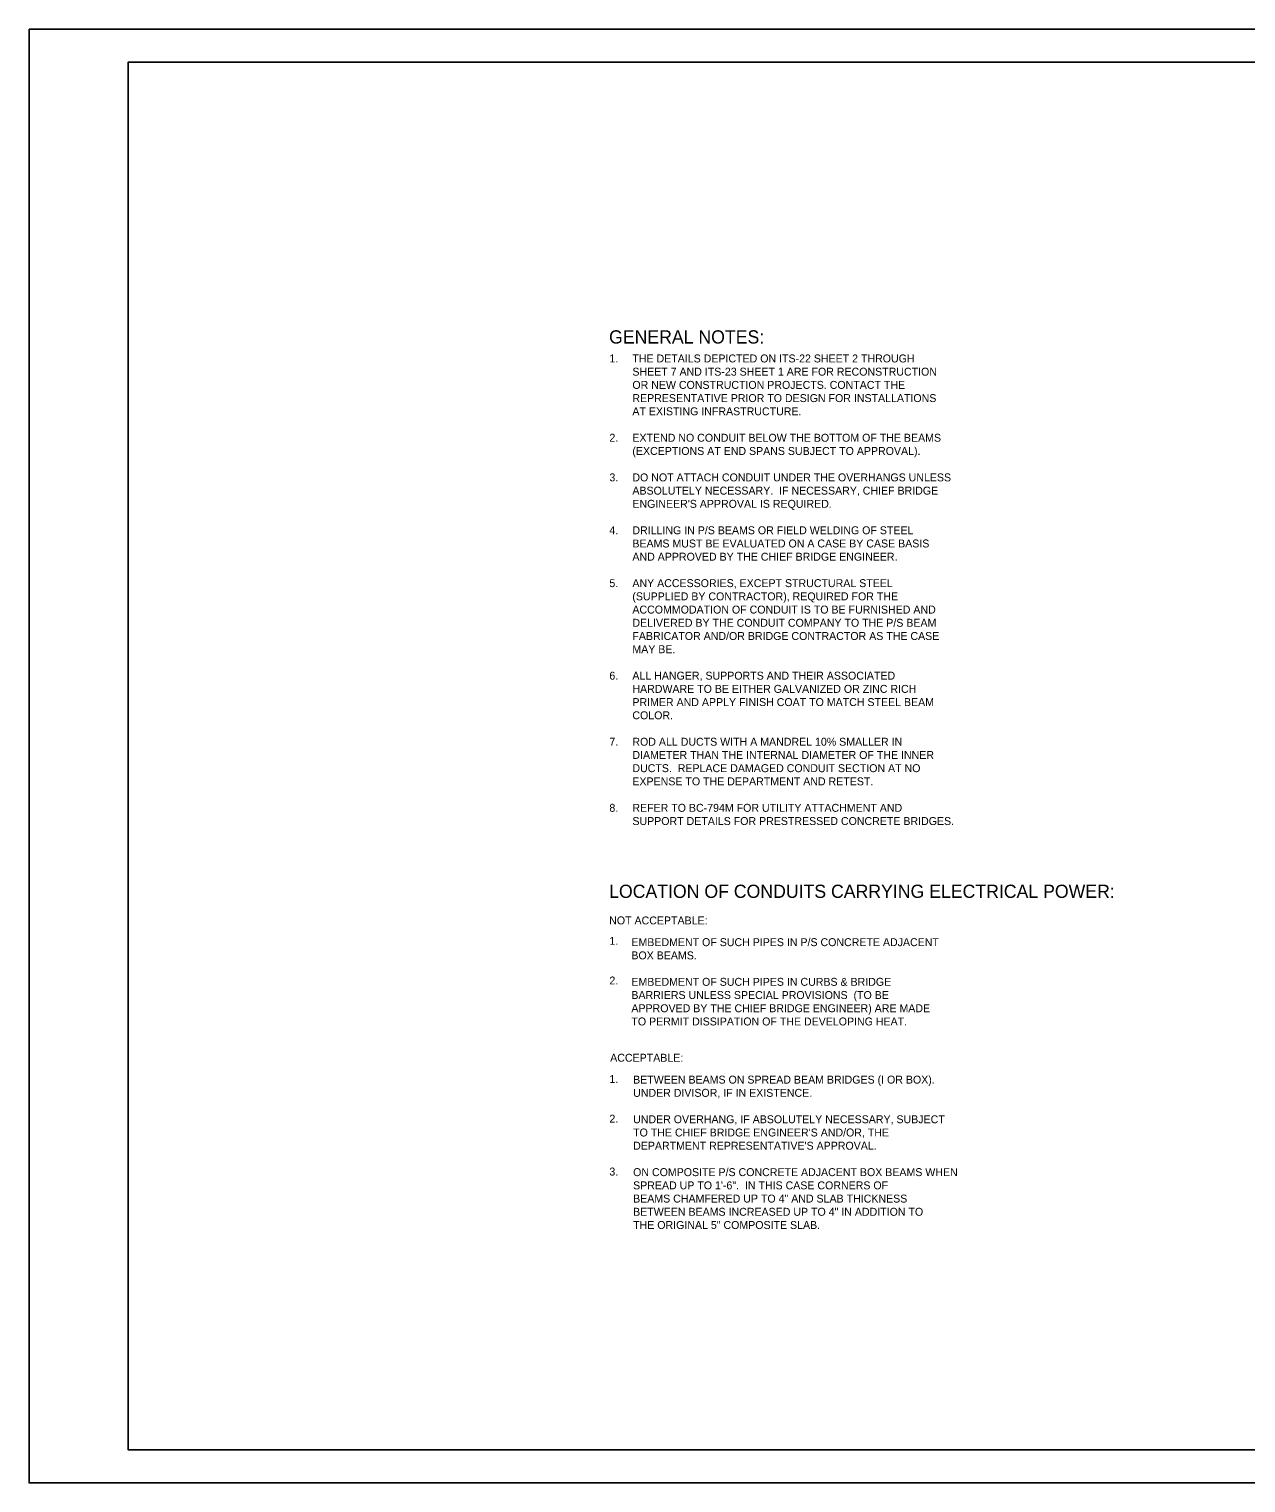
# Model space of a CAD drawing. Extents: x 1299104.8 to 1299141.6, y 239639.8 to 239661.8.
# Drawn here: x 1299104.8 to 1299123.22, y 239639.79 to 239661.79 of the extents above; entities that cross this region are included whole.
import ezdxf

# ---------------------------------------------------------------- set-up
doc = ezdxf.new("R2010")
doc.units = 0
for name, color, linetype in [('DIM TXT', 7, 'Continuous'), ('GS_plotshape_p', 7, 'Continuous'), ('Level 1', 7, 'Continuous')]:
    doc.layers.add(name, color=color, linetype=linetype)

msp = doc.modelspace()

# ---------------------------------------------------------------- linework, layer by layer
at = {"layer": 'GS_plotshape_p'}
msp.add_lwpolyline([(1299104.802, 239661.791), (1299138.802, 239661.791), (1299138.802, 239639.791), (1299104.802, 239639.791)], close=True, dxfattribs=at)
at = {"layer": 'Level 1'}
msp.add_lwpolyline([(1299138.302, 239640.291), (1299106.302, 239640.291), (1299106.302, 239661.291), (1299138.302, 239661.291)], close=True, dxfattribs=at)

# ---------------------------------------------------------------- texts
at = {"layer": 'DIM TXT'}
for s, height, p in [('GENERAL NOTES:', 0.2, (1299113.58, 239657.033)), ('1.', 0.12, (1299113.585, 239656.747)), ('THE DETAILS DEPICTED ON ITS-22 SHEET 2 THROUGH ', 0.12, (1299113.933, 239656.747)), ('SHEET 7 AND ITS-23 SHEET 1 ARE FOR RECONSTRUCTION ', 0.12, (1299113.933, 239656.547)), ('OR NEW CONSTRUCTION PROJECTS. CONTACT THE ', 0.12, (1299113.933, 239656.347)), ('REPRESENTATIVE PRIOR TO DESIGN FOR INSTALLATIONS ', 0.12, (1299113.933, 239656.147)), ('AT EXISTING INFRASTRUCTURE.', 0.12, (1299113.933, 239655.947)), ('2.', 0.12, (1299113.585, 239655.547)), ('(EXCEPTIONS AT END SPANS SUBJECT TO APPROVAL). ', 0.12, (1299113.933, 239655.347)), ('EXTEND NO CONDUIT BELOW THE BOTTOM OF THE BEAMS ', 0.12, (1299113.933, 239655.547)), ('3.', 0.12, (1299113.585, 239654.947)), ('DO NOT ATTACH CONDUIT UNDER THE OVERHANGS UNLESS ', 0.12, (1299113.933, 239654.947)), ('ABSOLUTELY NECESSARY.  IF NECESSARY, CHIEF BRIDGE ', 0.12, (1299113.933, 239654.747)), ("ENGINEER'S APPROVAL IS REQUIRED. ", 0.12, (1299113.933, 239654.547)), ('4.', 0.12, (1299113.585, 239654.147)), ('DRILLING IN P/S BEAMS OR FIELD WELDING OF STEEL ', 0.12, (1299113.933, 239654.147)), ('BEAMS MUST BE EVALUATED ON A CASE BY CASE BASIS ', 0.12, (1299113.933, 239653.947)), ('AND APPROVED BY THE CHIEF BRIDGE ENGINEER. ', 0.12, (1299113.933, 239653.747)), ('5.', 0.12, (1299113.585, 239653.347)), ('ANY ACCESSORIES, EXCEPT STRUCTURAL STEEL ', 0.12, (1299113.933, 239653.347)), ('(SUPPLIED BY CONTRACTOR), REQUIRED FOR THE ', 0.12, (1299113.933, 239653.147)), ('ACCOMMODATION OF CONDUIT IS TO BE FURNISHED AND ', 0.12, (1299113.933, 239652.947)), ('DELIVERED BY THE CONDUIT COMPANY TO THE P/S BEAM ', 0.12, (1299113.933, 239652.747)), ('FABRICATOR AND/OR BRIDGE CONTRACTOR AS THE CASE ', 0.12, (1299113.933, 239652.547)), ('MAY BE. ', 0.12, (1299113.933, 239652.347)), ('6.', 0.12, (1299113.585, 239651.947)), ('ALL HANGER, SUPPORTS AND THEIR ASSOCIATED ', 0.12, (1299113.933, 239651.947)), ('HARDWARE TO BE EITHER GALVANIZED OR ZINC RICH ', 0.12, (1299113.933, 239651.747)), ('PRIMER AND APPLY FINISH COAT TO MATCH STEEL BEAM ', 0.12, (1299113.933, 239651.547)), ('COLOR. ', 0.12, (1299113.933, 239651.347)), ('7.', 0.12, (1299113.585, 239650.947)), ('ROD ALL DUCTS WITH A MANDREL 10% SMALLER IN ', 0.12, (1299113.933, 239650.947)), ('DIAMETER THAN THE INTERNAL DIAMETER OF THE INNER ', 0.12, (1299113.933, 239650.747)), ('DUCTS.  REPLACE DAMAGED CONDUIT SECTION AT NO ', 0.12, (1299113.933, 239650.547)), ('EXPENSE TO THE DEPARTMENT AND RETEST.', 0.12, (1299113.933, 239650.347)), ('8.', 0.12, (1299113.585, 239649.947)), ('REFER TO BC-794M FOR UTILITY ATTACHMENT AND ', 0.12, (1299113.933, 239649.947)), ('SUPPORT DETAILS FOR PRESTRESSED CONCRETE BRIDGES.', 0.12, (1299113.933, 239649.747)), ('LOCATION OF CONDUITS CARRYING ELECTRICAL POWER:', 0.2, (1299113.581, 239648.644)), ('NOT ACCEPTABLE:', 0.12, (1299113.582, 239648.243)), ('1.', 0.12, (1299113.585, 239647.934)), ('EMBEDMENT OF SUCH PIPES IN P/S CONCRETE ADJACENT ', 0.12, (1299113.918, 239647.914)), ('BOX BEAMS.  ', 0.12, (1299113.918, 239647.714)), ('2.', 0.12, (1299113.585, 239647.334)), ('EMBEDMENT OF SUCH PIPES IN CURBS & BRIDGE ', 0.12, (1299113.918, 239647.314)), ('BARRIERS UNLESS SPECIAL PROVISIONS  (TO BE ', 0.12, (1299113.918, 239647.114)), ('APPROVED BY THE CHIEF BRIDGE ENGINEER) ARE MADE ', 0.12, (1299113.918, 239646.914)), ('TO PERMIT DISSIPATION OF THE DEVELOPING HEAT.', 0.12, (1299113.918, 239646.714)), ('ACCEPTABLE:', 0.12, (1299113.597, 239646.165)), ('1.', 0.12, (1299113.585, 239645.843)), ('BETWEEN BEAMS ON SPREAD BEAM BRIDGES (I OR BOX).  ', 0.12, (1299113.944, 239645.834)), ('UNDER DIVISOR, IF IN EXISTENCE. ', 0.12, (1299113.944, 239645.634)), ('2.', 0.12, (1299113.585, 239645.243)), ('UNDER OVERHANG, IF ABSOLUTELY NECESSARY, SUBJECT ', 0.12, (1299113.944, 239645.234)), ("TO THE CHIEF BRIDGE ENGINEER'S AND/OR, THE ", 0.12, (1299113.944, 239645.034)), ("DEPARTMENT REPRESENTATIVE'S APPROVAL. ", 0.12, (1299113.944, 239644.834)), ('3.', 0.12, (1299113.585, 239644.443)), ('ON COMPOSITE P/S CONCRETE ADJACENT BOX BEAMS WHEN ', 0.12, (1299113.944, 239644.434)), ('SPREAD UP TO 1\'-6".  IN THIS CASE CORNERS OF ', 0.12, (1299113.944, 239644.234)), ('BEAMS CHAMFERED UP TO 4" AND SLAB THICKNESS ', 0.12, (1299113.944, 239644.034)), ('BETWEEN BEAMS INCREASED UP TO 4" IN ADDITION TO ', 0.12, (1299113.944, 239643.834)), ('THE ORIGINAL 5" COMPOSITE SLAB.', 0.12, (1299113.944, 239643.634))]:
    msp.add_text(s, height=height, dxfattribs=at).set_placement(p)

doc.saveas('drawing.dxf')
